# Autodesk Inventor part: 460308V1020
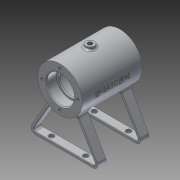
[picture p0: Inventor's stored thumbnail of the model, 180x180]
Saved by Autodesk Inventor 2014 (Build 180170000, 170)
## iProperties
Created: 2016-03
Part Number: 460308V1020
Material: 알루미늄 6061
Document SubType Name: Modeling
Designer: 703-15
Density: 2.71 g/cm^3
Appearance: 알루미늄 - 평지
Mass: 213.529 g
Surface Area: 336.749 cm^2
Volume: 78.7931 cm^3
Author: 703-15
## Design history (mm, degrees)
sketch "스케치4"
  geometry: L1 (16.613, -20)-(42.594, -65); L2 (-16.613, -20)-(-42.594, -65); L3 (0, 0)-(0, -4.858); L4 (-42.594, -65)-(42.594, -65); L5 (-16.613, -20)-(16.613, -20); A1 r 26 centre (0, 0) between (16.613, -20) and (-16.613, -20)
  constraints: 10 end point, 2 point on circle, 1 centre point, 1 coincident, 1 horizontal alignment, 1 parallel, 1 perpendicular, 1 vertical
  dimensions: "d14" = 30 deg angle of L2 L3; "d15" = 60 deg angle of L1 L2; "d16" = 65 distance from line of L3.start L4; "d17" = 52 diameter of A1; "d18" = 45 vertical distance of L1.end L1.start
extrude "돌출1" new body sketch "스케치4" distance "d19" = 10; taper "d20" = 0 deg
node "작업 평면3"
fillet "모깎기1" dims "d22" = 5
feature "쉘1" dims "d23" = 3
sketch "스케치6"
  geometry: L1 (-55, 26)-(15, 26); L2 (15, 26)-(15, 0); L3 (15, 0)-(-55, 0); L4 (-55, 0)-(-55, 26); L5 (0, -57.5)-(0, -20) reference; L6 (-20, 26)-(-20, 0); 1 further point
  constraints: 10 end point, 2 midpoint, 2 parallel, 1 horizontal, 1 perpendicular, 1 point on line
  dimensions: "d24" = 70 distance of L1.start L1.end; "d25" = 20 distance between parallel lines of L5 L6; "d26" = 26 distance of L1.end L2.end
revolve "회전2" sketch "스케치6" stored, may be unused: angle "d27" = 90 deg
fillet "모깎기2" dims "d38" = 3
node "작업 평면5"
  node "작업 평면4"
sketch "스케치8"
  geometry: L1 (15, -26)-(15, 26) reference; C1 r 6 at (-20, 0); 1 further point
  constraints: 1 centre point, 1 horizontal alignment
  dimensions: "d41" = 35 distance from line of L1 C1.centre; "d42" = 12 diameter of C1
extrude "돌출2" join sketch "스케치8" stored distance "d43" = 10; taper "d44" = 0 deg
hole "구멍2" diameter "d47" = 28; stored, may be unused: countersink angle "d51" = 90 deg, drill point angle "d53" = 118 deg; dims "d45" = 10, "d46" = 10, "d48" = 6, "d49" = 4, "d50" = 2, "d52" = 8
sketch "스케치9"
  geometry: L1 (-38, 21)-(-2, 21); L2 (1, 18)-(1, 0); L3 (1, 0)-(-41, 0); L4 (-41, 0)-(-41, 18); L5 (15, 14)-(15, -14) reference; A1 r 3 centre (-38, 18) between (-38, 21) and (-41, 18); A2 r 3 centre (-2, 18) between (1, 18) and (-2, 21); 3 further points
  constraints: 8 end point, 4 point on circle, 4 point on line, 4 tangent, 2 centre point, 2 parallel, 1 equal radius, 1 horizontal, 1 horizontal alignment, 1 perpendicular
  dimensions: "d54" = 42 distance of point (-41, 21) point (1, 21); "d55" = 21 distance of point (1, 21) L2.end; "d56" = 14 distance between parallel lines of L5 L2; "d57" = 3 radius of A1
revolve "회전3" sketch "스케치9" stored, may be unused: angle "d58" = 90 deg
hole "구멍3" diameter "d61" = 32; stored, may be unused: countersink angle "d65" = 90 deg, drill point angle "d67" = 0 deg; dims "d59" = 10, "d60" = 10, "d62" = 6, "d63" = 4, "d64" = 2, "d66" = 12
chamfer "모따기1" distance "d68" = 1; stored, may be unused: second distance "d69" = 2, angle "d70" = 45 deg
fillet "모깎기3" dims "d71" = 0.3
sketch "스케치10"
  geometry: C1 r 26 at (0, 0) reference; 1 further point
  constraints: 1 vertical alignment
  dimensions: "d72" = 21 distance of C1.centre point (0, 21)
hole "구멍4" sketch "스케치10" at (0, 21) diameter "d73" = 3.459; stored, may be unused: countersink angle "d77" = 90 deg, drill point angle "d79" = 118 deg; dims "d74" = 8, "d75" = 4, "d76" = 2, "d78" = 10
hole "구멍5" diameter "d85" = 5.188; stored, may be unused: countersink angle "d89" = 90 deg, drill point angle "d91" = 118 deg; dims "d83" = 10, "d84" = 10, "d86" = 8, "d87" = 4, "d88" = 2, "d90" = 10
fillet "모깎기4" dims "d92" = 2
node "작업 평면6"
sketch "스케치11"
  geometry: L1 (26, 15)-(-26, 15) reference; C1 r 5 at (0, -20); 1 further point
  constraints: 1 centre point, 1 vertical alignment
  dimensions: "d94" = 35 distance from line of L1 C1.centre; "d95" = 10 diameter of C1
extrude "돌출3" join sketch "스케치11" stored distance "d96" = 10; taper "d97" = 0 deg
fillet "모깎기5" dims "d98" = 2
hole "구멍6" diameter "d101" = 5.188; stored, may be unused: countersink angle "d105" = 90 deg, drill point angle "d107" = 118 deg; dims "d99" = 10, "d100" = 10, "d102" = 8, "d103" = 4, "d104" = 2, "d106" = 10
node "작업 평면7"
sketch "스케치12"
  geometry: L1 (-55, -26)-(-55, 26) reference; 2 further points
  constraints: 1 horizontal alignment, 1 other
  dimensions: "d109" = 35 distance from line of point (-20, 0) L1
feature "엠보싱1" sketch "스케치12" dims "d14" = 30 deg, "d15" = 60 deg, "d16" = 65, "d17" = 52, "d18" = 45, "d110" = 0.5, "d111" = 0
fillet "모깎기6" dims "d112" = 0.5
fillet "모깎기7" dims "d113" = 0.5
sketch "스케치14"
  geometry: L1 (0, 10)-(67.868, 10) reference; C1 r 3 at (53.934, 5); C2 r 3 at (13.934, 5); 1 further point
  constraints: 2 centre point, 1 equal radius, 1 horizontal alignment
  dimensions: "d124" = 6 diameter of C1; "d125" = 5 distance from line of L1 C1.centre; "d126" = 20 horizontal distance of point (33.934, 0) C2.centre; "d127" = 40 distance of C1.centre C2.centre
extrude "돌출4" cut sketch "스케치14" stored distance "d128" = 10; taper "d129" = 0 deg
node "솔리드2"
mirror "대칭1"
mirror "대칭3"
pattern_circular "원형 패턴1" dims angle "d81" = 360 deg
mirror "대칭4"
mirror "대칭6"
other parameters: "d39" = 15 deg, "d40" = -29, "d93" = 29, "d108" = 26
